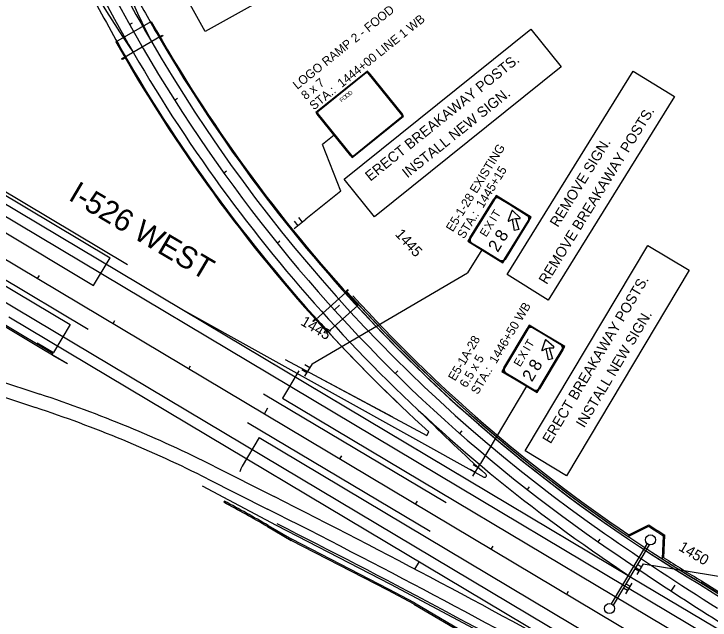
# Model space of a CAD drawing. Extents: x 2338610 to 2351914, y 366540 to 376484.
# Drawn here: x 2350110 to 2350900, y 367197 to 367886 of the extents above; entities that cross this region are included whole.
import ezdxf

# ---------------------------------------------------------------- set-up
doc = ezdxf.new("R2010")
doc.units = 0
for name, color, linetype in [('RD_HC_Cl', 7, 'Continuous'), ('RD_PD_Bridge', 7, 'Continuous'), ('RD_PD_Final_LnLine', 7, 'Continuous'), ('RD_PD_Final_TrvlWay', 7, 'Continuous'), ('RD_PD_GR', 7, 'Continuous'), ('RD_PD_GrRail', 7, 'Continuous'), ('RD_PD_MedBWall', 7, 'Continuous'), ('RD_PD_NOISE-WALL-GM', 7, 'Continuous'), ('RD_PD_PaveShd', 7, 'Continuous'), ('TR PM UNASSIGNED 3', 7, 'Continuous'), ('TR SN EXISTING - BREAK-AWAY SIGN SUPPORTS', 7, 'Continuous'), ('TR SN EXTRUDED PANEL SIGNS - GROUND MOUNTED', 7, 'Continuous'), ('TR SN EXTRUDED PANEL SIGNS- MOUNTED OVERHEAD', 7, 'Continuous'), ('TR SN UNASSIGNED 4', 7, 'Continuous'), ('TR SN UNASSIGNED 7', 7, 'Continuous')]:
    doc.layers.add(name, color=color, linetype=linetype)

msp = doc.modelspace()

# ---------------------------------------------------------------- linework, layer by layer
at = {"layer": 'RD_HC_Cl'}
msp.add_line((2346281.57, 369885.43), (2351112.4, 367003.22), dxfattribs=at)
for centre, radius, start, end in [((2351779.88, 368732.45), 1762, 199.58804, 235.18078), ((2352718.55, 370082.05), 3405.93, 235.18078, 239.17851)]:
    msp.add_arc(centre, radius, start, end, dxfattribs=at)
at = {"layer": 'RD_PD_Bridge'}
for p, q in [((2350225.6, 367854.46), (2350265.61, 367877.66)), ((2350235.53, 367837.1), (2350275.54, 367860.3)), ((2350486.94, 367569.69), (2350452.56, 367538.77)), ((2350500.4, 367554.9), (2350466.01, 367523.97))]:
    msp.add_line(p, q, dxfattribs=at)
for points in [[(2350275.54, 367860.3), (2350278.57, 367862.05), (2350279.07, 367861.19), (2350276.04, 367859.43)], [(2350232.5, 367835.34), (2350235.53, 367837.1), (2350236.03, 367836.23), (2350233, 367834.48)], [(2350486.28, 367570.44), (2350488.88, 367572.78), (2350489.55, 367572.03), (2350486.94, 367569.69)], [(2350449.28, 367537.17), (2350451.89, 367539.51), (2350452.56, 367538.77), (2350449.95, 367536.43)]]:
    msp.add_lwpolyline(points, close=True, dxfattribs=at)
for radius, start, end in [(1740, 209.44445, 222.62457), (1738.87, 209.44445, 222.62457), (1785.13, 209.46153, 222.6075), (1784, 209.46113, 222.6079)]:
    msp.add_arc((2351779.88, 368732.45), radius, start, end, dxfattribs=at)
at = {"layer": 'RD_PD_Final_LnLine'}
for p, q in [((2349253.37, 368063.47), (2351090.88, 366967.15)), ((2349842.01, 367810.08), (2351133.92, 367039.29)), ((2350811.17, 367245.82), (2351138.92, 367050.28))]:
    msp.add_line(p, q, dxfattribs=at)
for radius, start, end in [(1762, 199.58804, 235.18078), (1750, 204.21892, 210.03156), (1774, 204.4286, 210.1344)]:
    msp.add_arc((2351779.88, 368732.45), radius, start, end, dxfattribs=at)
at = {"layer": 'RD_PD_Final_TrvlWay'}
for p, q in [((2349855.88, 367815.78), (2350811.17, 367245.82)), ((2350302.42, 367549.36), (2350643.49, 367359.84)), ((2350302.42, 367549.36), (2350811.17, 367245.82)), ((2350103.89, 367542.04), (2350822.63, 367113.23)), ((2350103.89, 367542.04), (2350822.63, 367113.23)), ((2349890.06, 367536.2), (2350139.35, 367454)), ((2349881.67, 367522.12), (2350134.34, 367438.81)), ((2350336.89, 367372.15), (2350405.21, 367337.69)), ((2350329.69, 367357.86), (2350398.01, 367323.4)), ((2350570.05, 367263.92), (2350564.93, 367255.34))]:
    msp.add_line(p, q, dxfattribs=at)
for centre, radius, start, end in [((2351823.98, 368624.5), 1738, 200.3001, 206.22013), ((2351727.17, 368839.28), 1786, 208.17491, 213.95), ((2351779.88, 368732.45), 1750, 210.03156, 235.18078), ((2351779.88, 368732.45), 1774, 210.1344, 235.18078), ((2349688.27, 366086.07), 1440.39, 63.23618, 71.7499), ((2349688.27, 366086.07), 1424.39, 63.23618, 71.7499), ((2351833.75, 368685.99), 1778, 224.85366, 228.07614), ((2350644.52, 367361.56), 2, 239.17851, 50.36872), ((2345894.87, 358394.7), 10016, 60.797836, 63.236179), ((2345894.87, 358394.7), 10000, 60.800427, 63.236179), ((2352718.55, 370082.05), 3393.93, 235.18078, 237.7811), ((2352718.55, 370082.05), 3417.93, 235.18078, 236.07899)]:
    msp.add_arc(centre, radius, start, end, dxfattribs=at)
at = {"layer": 'RD_PD_GR'}
msp.add_arc((2351779.88, 368732.45), 1784, 222.23531, 226.36715, dxfattribs=at)
at = {"layer": 'RD_PD_GrRail'}
for p, q in [((2349869.74, 367821.48), (2350238.85, 367601.26)), ((2349966.48, 367663.62), (2350194.08, 367527.83)), ((2350145.34, 367503.2), (2350098.16, 367531.5)), ((2350170.68, 367488.6), (2350145.34, 367503.2)), ((2350170.68, 367488.6), (2350153.39, 367498.47)), ((2350417.94, 367493.3), (2350539.75, 367428.31)), ((2350600.88, 367330.46), (2350393.35, 367453.88)), ((2350375.15, 367421.81), (2350582.67, 367298.39)), ((2350408.06, 367304.88), (2350324.17, 367349.46)), ((2350537.97, 367237.9), (2350408.06, 367304.88)), ((2350631.98, 367187.85), (2350537.94, 367237.91))]:
    msp.add_line(p, q, dxfattribs=at)
at = {"layer": 'RD_PD_MedBWall'}
for p, q in [((2350889.7, 367240.11), (2351016.63, 367159.72)), ((2350888.48, 367238.13), (2351015.38, 367157.75))]:
    msp.add_line(p, q, dxfattribs=at)
for radius, start, end in [(1740, 221.96556, 239.18289), (1737.67, 221.96558, 239.18392)]:
    msp.add_arc((2351779.88, 368732.45), radius, start, end, dxfattribs=at)
at = {"layer": 'RD_PD_NOISE-WALL-GM'}
for p, q in [((2350348.86, 367332.47), (2350348.16, 367331.14)), ((2350397.9, 367303.48), (2350424.62, 367287.9)), ((2350398.66, 367304.77), (2350425.37, 367289.2)), ((2350807.51, 367292.32), (2350830.9, 367303.93)), ((2350808.14, 367294.31), (2350831.01, 367305.66)), ((2350534.44, 367231.28), (2350424.59, 367287.92)), ((2350535.13, 367232.61), (2350425.28, 367289.25)), ((2350846.3, 367266.87), (2350847.64, 367292.96)), ((2350847.88, 367268.24), (2350849.18, 367293.74)), ((2350889.97, 367240.54), (2351016.9, 367160.14)), ((2350890.77, 367241.8), (2351017.7, 367161.41)), ((2350564.93, 367216.75), (2350535.13, 367232.61)), ((2350564.22, 367215.42), (2350534.42, 367231.29)), ((2350564.93, 367216.75), (2351270.05, 366804.01)), ((2350564.17, 367215.45), (2351269.29, 366802.71))]:
    msp.add_line(p, q, dxfattribs=at)
for centre, radius, start, end in [((2351779.88, 368732.45), 1737.67, 222.23531, 235.97297), ((2351779.88, 368732.45), 1735.67, 222.23531, 235.9535), ((2349688.27, 366086.07), 1409.14, 59.76184, 62.07634), ((2349688.27, 366086.07), 1410.64, 59.76184, 62.07634), ((2351779.88, 368732.45), 1715, 236.40354, 237.0722), ((2351779.88, 368732.45), 1713.5, 236.37459, 237.10116), ((2351779.88, 368732.45), 1737.67, 237.50277, 239.18392), ((2351779.88, 368732.45), 1735.67, 237.52224, 239.18392)]:
    msp.add_arc(centre, radius, start, end, dxfattribs=at)
at = {"layer": 'RD_PD_PaveShd'}
for p, q in [((2349506.94, 367991.36), (2350200.36, 367577.64)), ((2349475.16, 367949.69), (2350173.67, 367533.02)), ((2349979.3, 367752.13), (2350219.13, 367609.11)), ((2350200.36, 367577.64), (2350219.13, 367609.11)), ((2350098.77, 367533.46), (2350154.44, 367500.24)), ((2350173.67, 367533.02), (2350154.95, 367501.34)), ((2350136.2, 367512.27), (2350154.95, 367501.34)), ((2350433.55, 367480.63), (2350415.03, 367449.57)), ((2350435.51, 367483.92), (2350578.95, 367407.14)), ((2350415.03, 367449.57), (2351125.72, 367025.55)), ((2350578.95, 367407.14), (2350581.18, 367411.17)), ((2350388.55, 367404.82), (2350369.11, 367372.22)), ((2350388.55, 367404.82), (2351099.08, 366980.89)), ((2350367.5, 367369.09), (2350366.5, 367365.65)), ((2350369.11, 367372.22), (2350367.5, 367369.09)), ((2350888.59, 367238.06), (2351015.36, 367157.77))]:
    msp.add_line(p, q, dxfattribs=at)
for centre, radius, start, end in [((2351779.88, 368732.45), 1784, 207.24172, 210.12524), ((2351779.88, 368732.45), 1740, 208.07437, 210.08112), ((2351779.88, 368732.45), 1740, 222.23531, 239.17851), ((2351779.88, 368732.45), 1784, 222.23531, 227.78502), ((2345894.87, 358394.7), 9990, 60.800427, 63.136738)]:
    msp.add_arc(centre, radius, start, end, dxfattribs=at)
at = {"layer": 'TR SN EXISTING - BREAK-AWAY SIGN SUPPORTS'}
for points in [[(2350300.34, 367914.05), (2350537.85, 368046.53), (2350564.61, 367998.57), (2350327.09, 367866.09)], [(2350484.92, 367698.46), (2350696.89, 367868.86), (2350731.3, 367826.06), (2350519.33, 367655.66)], [(2350670.07, 367589.89), (2350813.29, 367821.08), (2350859.97, 367792.16), (2350716.75, 367560.97)], [(2350690.42, 367389.46), (2350829.76, 367623.01), (2350876.92, 367594.88), (2350737.58, 367361.32)]]:
    msp.add_lwpolyline(points, close=True, dxfattribs=at)
at = {"layer": 'TR SN EXTRUDED PANEL SIGNS - GROUND MOUNTED'}
for p, q in [((2350509.5, 367819.63), (2350509.99, 367819.02)), ((2350512.19, 367818.78), (2350512.8, 367819.27)), ((2350454.31, 367772.25), (2350454.92, 367772.74)), ((2350455.16, 367774.94), (2350454.67, 367775.55)), ((2350550.15, 367769.06), (2350550.64, 367768.45)), ((2350551, 367771.75), (2350550.39, 367771.26)), ((2350473.41, 367748.49), (2350460.22, 367737.89)), ((2350481.19, 367684.81), (2350460.22, 367737.89)), ((2350493.12, 367725.22), (2350492.51, 367724.73)), ((2350495.81, 367724.37), (2350495.32, 367724.98)), ((2350481.19, 367684.81), (2350441.31, 367652.75)), ((2350657.42, 367679.68), (2350625.31, 367627.85)), ((2350654.95, 367675.7), (2350655.61, 367675.28)), ((2350673.36, 367669.8), (2350657.42, 367679.68)), ((2350660.99, 367676.55), (2350661.4, 367677.21)), ((2350697.29, 367654.98), (2350673.36, 367669.8)), ((2350675.17, 367662.34), (2350675.72, 367662.14)), ((2350675.72, 367662.14), (2350676.12, 367662.57)), ((2350428.08, 367650.6), (2350432.25, 367645.43)), ((2350428.3, 367642.29), (2350441.31, 367652.75)), ((2350433.09, 367654.63), (2350437.27, 367649.43)), ((2350671.58, 367651.13), (2350671.03, 367651.34)), ((2350671.85, 367650.61), (2350671.58, 367651.13)), ((2350684.33, 367654.12), (2350684.32, 367653.54)), ((2350684.73, 367654.55), (2350684.33, 367654.12)), ((2350684.94, 367635.05), (2350697.29, 367654.98)), ((2350693.3, 367657.45), (2350692.89, 367656.79)), ((2350694.15, 367651.41), (2350694.82, 367651)), ((2350665.18, 367603.15), (2350684.94, 367635.05)), ((2350684.94, 367635.05), (2350684.94, 367635.05)), ((2350684.94, 367635.05), (2350684.94, 367635.05)), ((2350625.31, 367627.85), (2350641.25, 367617.97)), ((2350628.44, 367631.43), (2350627.78, 367631.84)), ((2350629.29, 367625.38), (2350629.71, 367626.05)), ((2350641.25, 367617.97), (2350625.06, 367591.83)), ((2350641.25, 367617.97), (2350665.18, 367603.15)), ((2350641.25, 367617.97), (2350641.25, 367617.97)), ((2350641.25, 367617.97), (2350641.25, 367617.97)), ((2350661.6, 367606.29), (2350661.19, 367605.62)), ((2350665.18, 367603.15), (2350665.18, 367603.15)), ((2350665.18, 367603.15), (2350665.18, 367603.15)), ((2350667.65, 367607.14), (2350666.98, 367607.55)), ((2350448.47, 367488.51), (2350625.06, 367591.83)), ((2350448.42, 367488.55), (2350439.68, 367474.32)), ((2350440.15, 367487.72), (2350445.81, 367484.24)), ((2350436.79, 367482.24), (2350442.47, 367478.75)), ((2350692.16, 367463.16), (2350639.74, 367375.29)), ((2350631.18, 367360.95), (2350639.74, 367375.29)), ((2350631.38, 367374.19), (2350637.11, 367370.77)), ((2350628.08, 367368.67), (2350633.79, 367365.26))]:
    msp.add_line(p, q, dxfattribs=at)
for points in [[(2350493.98, 367722.9), (2350552.47, 367769.92), (2350511.33, 367821.09), (2350452.84, 367774.08), (2350493.98, 367722.9), (2350493.98, 367722.9)], [(2350509.99, 367819.02), (2350455.16, 367774.94), (2350454.67, 367775.55), (2350509.5, 367819.63), (2350509.99, 367819.02), (2350509.99, 367819.02)], [(2350550.39, 367771.26), (2350512.19, 367818.78), (2350512.8, 367819.27), (2350551, 367771.75), (2350550.39, 367771.26), (2350550.39, 367771.26)], [(2350454.92, 367772.74), (2350493.12, 367725.22), (2350492.51, 367724.73), (2350454.31, 367772.25), (2350454.92, 367772.74), (2350454.92, 367772.74)], [(2350495.32, 367724.98), (2350550.15, 367769.06), (2350550.64, 367768.45), (2350495.81, 367724.37), (2350495.32, 367724.98), (2350495.32, 367724.98)], [(2350655.61, 367675.28), (2350628.44, 367631.43), (2350627.78, 367631.84), (2350654.95, 367675.7), (2350655.61, 367675.28), (2350655.61, 367675.28)], [(2350672.95, 367669.14), (2350660.99, 367676.55), (2350661.4, 367677.21), (2350673.36, 367669.8), (2350672.95, 367669.14), (2350672.95, 367669.14)], [(2350692.89, 367656.79), (2350672.95, 367669.14), (2350673.36, 367669.8), (2350693.3, 367657.45), (2350692.89, 367656.79), (2350692.89, 367656.79)], [(2350675.72, 367662.14), (2350675.17, 367662.34), (2350671.03, 367651.34), (2350671.58, 367651.13), (2350671.85, 367650.61), (2350676.11, 367652.79), (2350679.53, 367653.6), (2350684.32, 367653.54), (2350684.33, 367654.12), (2350684.73, 367654.55), (2350676.12, 367662.57), (2350675.72, 367662.14), (2350675.72, 367662.14)], [(2350683.1, 367640.99), (2350678.53, 367639.91), (2350676.11, 367652.79), (2350679.53, 367653.6), (2350683.1, 367640.99), (2350683.1, 367640.99)], [(2350684.27, 367635.46), (2350694.15, 367651.41), (2350694.82, 367651), (2350684.94, 367635.05), (2350684.27, 367635.46), (2350684.27, 367635.46)], [(2350666.98, 367607.55), (2350684.27, 367635.46), (2350684.94, 367635.05), (2350667.65, 367607.14), (2350666.98, 367607.55), (2350666.98, 367607.55)], [(2350629.71, 367626.05), (2350641.67, 367618.64), (2350641.25, 367617.97), (2350629.29, 367625.38), (2350629.71, 367626.05), (2350629.71, 367626.05)], [(2350641.67, 367618.64), (2350661.6, 367606.29), (2350661.19, 367605.62), (2350641.25, 367617.97), (2350641.67, 367618.64), (2350641.67, 367618.64)]]:
    msp.add_lwpolyline(points, close=True, dxfattribs=at)
for centre, radius, start, end in [((2350510.97, 367817.8), 2.35, 38.79484, 128.79505), ((2350510.97, 367817.8), 1.56, 38.79484, 128.79505), ((2350456.14, 367773.72), 2.35, 128.79505, 218.79469), ((2350456.14, 367773.72), 1.56, 128.79505, 218.79469), ((2350549.17, 367770.28), 1.56, 308.7949, 38.79511), ((2350549.17, 367770.28), 2.35, 308.7949, 38.79511), ((2350494.34, 367726.2), 2.35, 218.79469, 308.7949), ((2350494.34, 367726.2), 1.56, 218.79469, 308.7949), ((2350658.93, 367673.23), 4.69, 58.22188, 148.22209), ((2350658.93, 367673.23), 3.91, 58.22188, 148.22209), ((2350675.72, 367662.14), 0.586, 47.04374, 159.39962), ((2350671.58, 367651.13), 0.586, 159.39992, 297.18424), ((2350684.33, 367654.12), 0.586, 269.26, 47.04374), ((2350690.83, 367653.47), 3.91, 328.22194, 58.22215), ((2350690.83, 367653.47), 4.69, 328.22194, 58.22215), ((2350631.76, 367629.37), 4.69, 148.22209, 238.22173), ((2350631.76, 367629.37), 3.91, 148.22209, 238.22173), ((2350663.66, 367609.61), 4.69, 238.22173, 328.22194), ((2350663.66, 367609.61), 3.91, 238.22173, 328.22194)]:
    msp.add_arc(centre, radius, start, end, dxfattribs=at)
at = {"layer": 'TR SN EXTRUDED PANEL SIGNS- MOUNTED OVERHEAD'}
for p, q in [((2350695.21, 367532.34), (2350663.97, 367479.98)), ((2350711.32, 367522.73), (2350695.21, 367532.34)), ((2350692.81, 367528.31), (2350693.48, 367527.91)), ((2350698.84, 367529.27), (2350699.24, 367529.94)), ((2350735.48, 367508.31), (2350711.32, 367522.73)), ((2350713.25, 367515.3), (2350713.8, 367515.1)), ((2350713.8, 367515.1), (2350714.19, 367515.54)), ((2350723.47, 367488.17), (2350735.48, 367508.31)), ((2350731.46, 367510.71), (2350731.06, 367510.04)), ((2350709.85, 367504.03), (2350709.3, 367504.22)), ((2350710.12, 367503.51), (2350709.85, 367504.03)), ((2350722.93, 367507.67), (2350722.54, 367507.23)), ((2350722.54, 367507.23), (2350722.54, 367506.65)), ((2350732.41, 367504.68), (2350733.08, 367504.28)), ((2350704.25, 367455.95), (2350723.47, 367488.17)), ((2350723.47, 367488.17), (2350723.47, 367488.17)), ((2350723.47, 367488.17), (2350723.47, 367488.17)), ((2350663.97, 367479.98), (2350680.08, 367470.37)), ((2350667.04, 367483.61), (2350666.37, 367484.01)), ((2350668, 367477.58), (2350668.4, 367478.25)), ((2350680.08, 367470.37), (2350704.25, 367455.95)), ((2350680.08, 367470.37), (2350680.08, 367470.37)), ((2350680.08, 367470.37), (2350680.08, 367470.37)), ((2350700.62, 367459.02), (2350700.22, 367458.35)), ((2350704.25, 367455.95), (2350704.25, 367455.95)), ((2350704.25, 367455.95), (2350704.25, 367455.95)), ((2350706.65, 367459.98), (2350705.98, 367460.38)), ((2350828.92, 367284.24), (2350788.28, 367215.75)), ((2350831.23, 367282.92), (2350790.49, 367214.26)), ((2350819.73, 367253.01), (2350815.11, 367255.75)), ((2350824.65, 367261.29), (2350817.47, 367249.19)), ((2350822.5, 367257.66), (2350817.87, 367260.41)), ((2350824.65, 367261.29), (2350971.16, 367237.06)), ((2350811.6, 367239.3), (2350804.43, 367227.21)), ((2350806.69, 367231.02), (2350802.06, 367233.77)), ((2350809.45, 367235.68), (2350804.82, 367238.43))]:
    msp.add_line(p, q, dxfattribs=at)
for points in [[(2350693.48, 367527.91), (2350667.04, 367483.61), (2350666.37, 367484.01), (2350692.81, 367528.31), (2350693.48, 367527.91), (2350693.48, 367527.91)], [(2350710.92, 367522.06), (2350698.84, 367529.27), (2350699.24, 367529.94), (2350711.32, 367522.73), (2350710.92, 367522.06), (2350710.92, 367522.06)], [(2350731.06, 367510.04), (2350710.92, 367522.06), (2350711.32, 367522.73), (2350731.46, 367510.71), (2350731.06, 367510.04), (2350731.06, 367510.04)], [(2350713.8, 367515.1), (2350713.25, 367515.3), (2350709.3, 367504.22), (2350709.85, 367504.03), (2350710.12, 367503.51), (2350714.35, 367505.77), (2350717.76, 367506.63), (2350722.54, 367506.65), (2350722.54, 367507.23), (2350722.93, 367507.67), (2350714.19, 367515.54), (2350713.8, 367515.1), (2350713.8, 367515.1)], [(2350721.53, 367494.08), (2350716.98, 367492.93), (2350714.35, 367505.77), (2350717.76, 367506.63), (2350721.53, 367494.08), (2350721.53, 367494.08)], [(2350722.8, 367488.57), (2350732.41, 367504.68), (2350733.08, 367504.28), (2350723.47, 367488.17), (2350722.8, 367488.57), (2350722.8, 367488.57)], [(2350705.98, 367460.38), (2350722.8, 367488.57), (2350723.47, 367488.17), (2350706.65, 367459.98), (2350705.98, 367460.38), (2350705.98, 367460.38)], [(2350668.4, 367478.25), (2350680.48, 367471.04), (2350680.08, 367470.37), (2350668, 367477.58), (2350668.4, 367478.25), (2350668.4, 367478.25)], [(2350680.48, 367471.04), (2350700.62, 367459.02), (2350700.22, 367458.35), (2350680.08, 367470.37), (2350680.48, 367471.04), (2350680.48, 367471.04)]]:
    msp.add_lwpolyline(points, close=True, dxfattribs=at)
for centre in [(2350832.81, 367288.41), (2350786.28, 367210.42)]:
    msp.add_circle(centre, 5.7, dxfattribs=at)
for centre, radius, start, end in [((2350696.83, 367525.91), 4.69, 59.17851, 149.17872), ((2350696.83, 367525.91), 3.91, 59.17851, 149.17872), ((2350713.8, 367515.1), 0.586, 48.00037, 160.35625), ((2350729.05, 367506.69), 3.91, 329.17857, 59.17878), ((2350729.05, 367506.69), 4.69, 329.17857, 59.17878), ((2350709.85, 367504.03), 0.586, 160.35655, 298.14087), ((2350722.54, 367507.23), 0.586, 270.21662, 48.00037), ((2350670.4, 367481.61), 4.69, 149.17872, 239.17836), ((2350670.4, 367481.61), 3.91, 149.17872, 239.17836), ((2350702.62, 367462.38), 4.69, 239.17836, 329.17857), ((2350702.62, 367462.38), 3.91, 239.17836, 329.17857)]:
    msp.add_arc(centre, radius, start, end, dxfattribs=at)
at = {"layer": 'TR SN UNASSIGNED 7'}
for p, q in [((2350241.07, 367874.13), (2350244.57, 367876.08)), ((2350292.24, 367788.22), (2350295.62, 367790.37)), ((2350348.19, 367705.36), (2350351.44, 367707.69)), ((2350408.76, 367625.8), (2350411.87, 367628.32)), ((2350136.65, 367585.38), (2350138.7, 367588.82)), ((2350473.74, 367549.81), (2350479.67, 367555.18)), ((2350222.52, 367534.15), (2350224.57, 367537.58)), ((2350308.4, 367482.91), (2350310.45, 367486.35)), ((2350542.92, 367477.63), (2350545.73, 367480.47)), ((2350394.28, 367431.67), (2350398.38, 367438.54)), ((2350616.09, 367409.48), (2350618.74, 367412.49)), ((2350480.15, 367380.44), (2350482.2, 367383.87)), ((2350693.01, 367345.6), (2350695.48, 367348.75)), ((2350566.03, 367329.2), (2350568.08, 367332.64)), ((2350773.43, 367286.18), (2350775.71, 367289.46)), ((2350651.91, 367277.96), (2350653.96, 367281.4)), ((2350856.34, 367230.28), (2350860.72, 367236.98)), ((2350737.78, 367226.73), (2350739.83, 367230.16))]:
    msp.add_line(p, q, dxfattribs=at)

# ---------------------------------------------------------------- texts
at = {"layer": 'TR PM UNASSIGNED 3'}
for s, rotation, p in [('LOGO RAMP 2 - FOOD', 38.79484, (2350431.64, 367799.76)), ('STA.:  1444+00 LINE 1 WB', 38.79484, (2350450.44, 367776.37)), ('8 x 7', 38.79484, (2350441.04, 367788.06)), ('E5-1-28 EXISTING', 58.22188, (2350608.23, 367637.78)), ('STA.:  1445+15', 58.22188, (2350620.98, 367629.88)), ('STA.:  1446+50 WB', 59.17851, (2350636.62, 367452.85)), ('E5-1A-28', 59.17851, (2350610.86, 367468.22)), ('6.5 x 5', 59.17851, (2350623.74, 367460.54))]:
    msp.add_text(s, height=10, rotation=rotation, dxfattribs=at).set_placement(p)
at = {"layer": 'TR SN EXISTING - BREAK-AWAY SIGN SUPPORTS'}
for s, rotation, p in [('ERECT BREAKAWAY POSTS.', 38.79492, (2350514.64, 367695.4)), ('INSTALL NEW SIGN.', 38.79492, (2350556.64, 367699.09)), ('REMOVE BREAKAWAY POSTS.', 58.22196, (2350714.96, 367577.96)), ('REMOVE SIGN.', 58.22196, (2350727.63, 367642.91)), ('ERECT BREAKAWAY POSTS.', 59.17859, (2350719.34, 367396.94)), ('INSTALL NEW SIGN.', 59.17859, (2350757.43, 367415.03))]:
    msp.add_text(s, height=11.7187, rotation=rotation, dxfattribs=at).set_placement(p)
at = {"layer": 'TR SN EXTRUDED PANEL SIGNS - GROUND MOUNTED'}
for s, height, rotation, p in [('O', 4.69, 38.79484, (2350484.85, 367787.77)), ('O', 4.69, 38.79484, (2350488.1, 367790.39)), ('D', 4.69, 38.79484, (2350491.53, 367793.15)), ('F', 4.69, 38.79484, (2350481.94, 367785.43)), ('T', 9.38, 58.22188, (2350659.49, 367653.35)), ('X', 9.38, 58.22188, (2350651.34, 367640.19)), ('I', 9.38, 58.22188, (2350657.11, 367649.51)), ('E', 9.38, 58.22188, (2350646.19, 367631.87)), ('8', 14.07, 58.22188, (2350666.72, 367626.43)), ('2', 14.07, 58.22188, (2350659.29, 367614.43))]:
    msp.add_text(s, height=height, rotation=rotation, dxfattribs=at).set_placement(p)
at = {"layer": 'TR SN EXTRUDED PANEL SIGNS- MOUNTED OVERHEAD'}
for s, height, p in [('T', 9.38, (2350697.72, 367506.04)), ('I', 9.38, (2350695.41, 367502.16)), ('X', 9.38, (2350689.79, 367492.75)), ('E', 9.38, (2350684.78, 367484.35)), ('8', 14.07, (2350705.4, 367479.25)), ('2', 14.07, (2350698.17, 367467.13))]:
    msp.add_text(s, height=height, rotation=59.17851, dxfattribs=at).set_placement(p)
at = {"layer": 'TR SN UNASSIGNED 4'}
msp.add_text('I-526 WEST', height=25, rotation=329.40941, dxfattribs=at).set_placement((2350170.52, 367675.48))
at = {"layer": 'TR SN UNASSIGNED 7'}
for s, rotation, p in [('1445', 312.15914, (2350542.03, 367635.3)), ('1445', 329.17851, (2350434.55, 367533.41)), ('1450', 329.17851, (2350863.82, 367277.29))]:
    msp.add_text(s, height=12, rotation=rotation, dxfattribs=at).set_placement(p)

doc.saveas('drawing.dxf')
